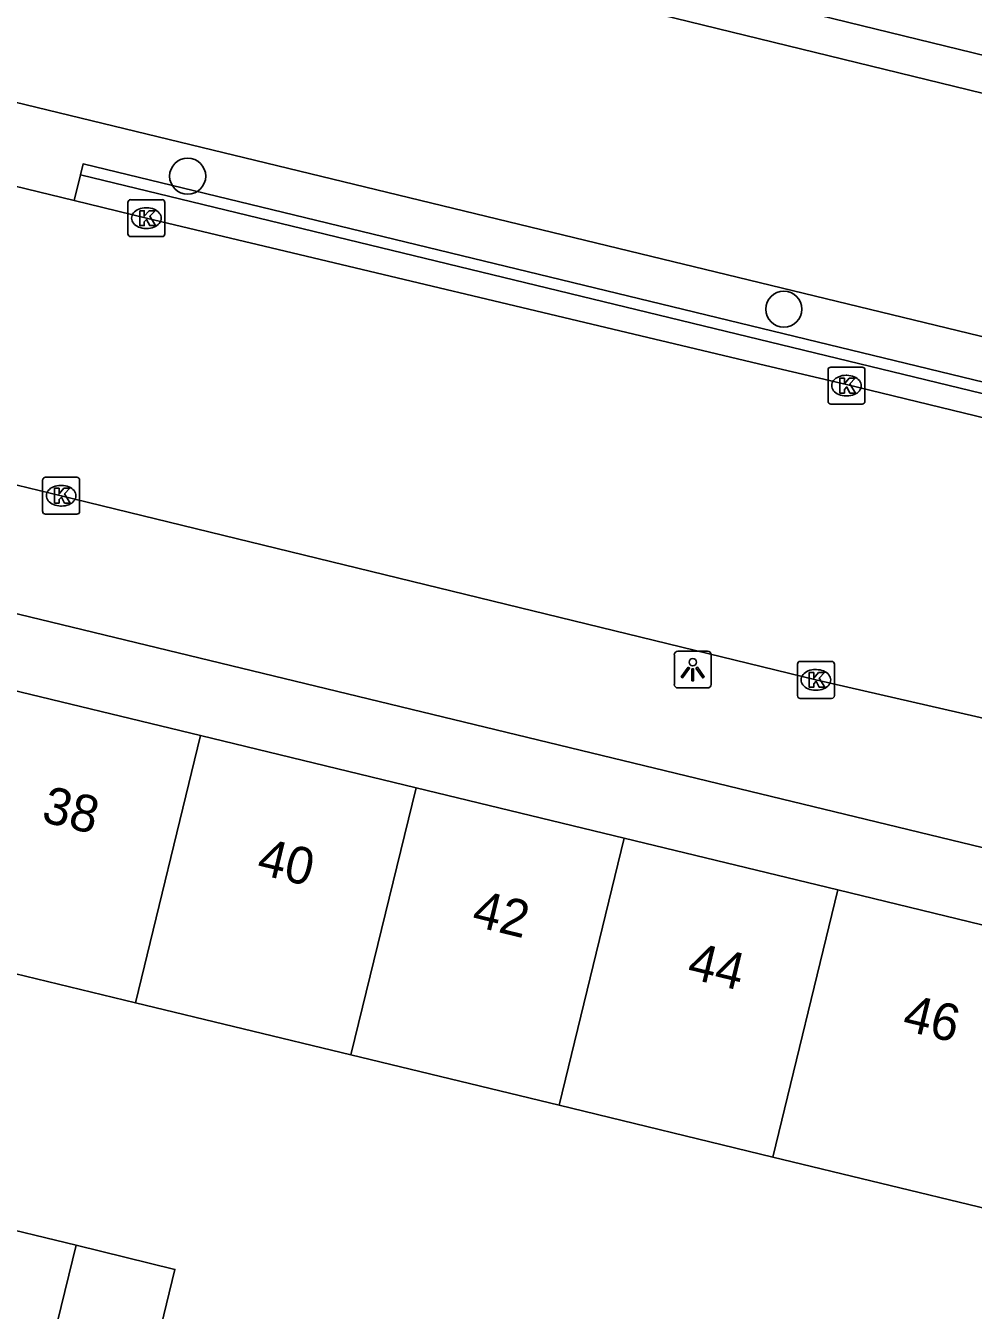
# Model space of a CAD drawing. Extents: x 162812 to 163818, y 381639 to 382470.
# Drawn here: x 163350.81 to 163376.49, y 382263.66 to 382298.47 of the extents above; entities that cross this region are included whole.
import ezdxf

# ---------------------------------------------------------------- set-up
doc = ezdxf.new("R2010")
doc.units = 0
for name, color, linetype in [('IMGEO_Boom', 7, 'Continuous'), ('IMGEO_Groenvoorziening', 7, 'Continuous'), ('IMGEO_Haag', 7, 'Continuous'), ('IMGEO_Kolk', 7, 'Continuous'), ('IMGEO_Lichtpunt', 7, 'Continuous'), ('IMGEO_Muur', 7, 'Continuous'), ('IMGEO_Pand', 7, 'Continuous'), ('IMGEO_Pand_nummerreeks', 7, 'Continuous'), ('IMGEO_Rijbaan_lokaal_gesloten', 7, 'Continuous'), ('IMGEO_Voetpad_open', 7, 'Continuous'), ('IMGEO_Waterloop', 7, 'Continuous')]:
    doc.layers.add(name, color=color, linetype=linetype)

msp = doc.modelspace()

# ---------------------------------------------------------------- linework, layer by layer
at = {"layer": 'IMGEO_Boom'}
for centre in [(163355.197, 382294.391), (163371.351, 382290.786)]:
    msp.add_circle(centre, 0.489, dxfattribs=at)
at = {"layer": 'IMGEO_Groenvoorziening'}
for points in [[(163321.09, 382310.224), (163499.763, 382266.618), (163515.133, 382262.867)], [(163454.527, 382271.183), (163319.582, 382303.902)], [(163388.463, 382285.657), (163388.534, 382285.949), (163352.363, 382294.719), (163352.293, 382294.427)]]:
    msp.add_lwpolyline(points, dxfattribs=at)
at = {"layer": 'IMGEO_Haag'}
for points in [[(163352.293, 382294.427), (163352.124, 382293.728)], [(163352.293, 382294.427), (163388.463, 382285.657)]]:
    msp.add_lwpolyline(points, dxfattribs=at)
at = {"layer": 'IMGEO_Kolk'}
for p, q in [((163353.652, 382293.752), (163354.504, 382293.752)), ((163353.577, 382292.826), (163353.577, 382293.678)), ((163354.065, 382293.532), (163354.09, 382293.532)), ((163354.578, 382293.678), (163354.578, 382292.826)), ((163354.504, 382292.752), (163353.652, 382292.752)), ((163354.088, 382292.972), (163354.063, 382292.972)), ((163372.624, 382289.213), (163373.476, 382289.213)), ((163372.549, 382288.287), (163372.549, 382289.139)), ((163373.037, 382288.993), (163373.062, 382288.993)), ((163373.55, 382289.139), (163373.55, 382288.287)), ((163373.476, 382288.213), (163372.624, 382288.213)), ((163373.06, 382288.433), (163373.035, 382288.433)), ((163351.268, 382285.305), (163351.268, 382286.157)), ((163351.343, 382286.231), (163352.195, 382286.231)), ((163352.269, 382286.157), (163352.269, 382285.305)), ((163351.756, 382286.011), (163351.781, 382286.011)), ((163351.779, 382285.451), (163351.754, 382285.451)), ((163352.195, 382285.231), (163351.343, 382285.231)), ((163371.72, 382280.314), (163371.72, 382281.166)), ((163371.795, 382281.24), (163372.647, 382281.24)), ((163372.721, 382281.166), (163372.721, 382280.314)), ((163372.208, 382281.02), (163372.233, 382281.02)), ((163372.231, 382280.46), (163372.206, 382280.46)), ((163372.647, 382280.24), (163371.795, 382280.24))]:
    msp.add_line(p, q, dxfattribs=at)
for points in [[(163353.652, 382293.752), (163354.504, 382293.752)], [(163353.577, 382292.826), (163353.577, 382293.678)], [(163353.898, 382293.452), (163354.021, 382293.452), (163354.021, 382293.301), (163354.151, 382293.452), (163354.315, 382293.452), (163354.169, 382293.301), (163354.322, 382293.052), (163354.17, 382293.052), (163354.085, 382293.216), (163354.021, 382293.149), (163354.021, 382293.052), (163353.898, 382293.052), (163353.898, 382293.452)], [(163354.578, 382293.678), (163354.578, 382292.826)], [(163354.504, 382292.752), (163353.652, 382292.752)], [(163372.624, 382289.213), (163373.476, 382289.213)], [(163372.549, 382288.287), (163372.549, 382289.139)], [(163372.87, 382288.913), (163372.993, 382288.913), (163372.993, 382288.762), (163373.123, 382288.913), (163373.287, 382288.913), (163373.141, 382288.762), (163373.294, 382288.513), (163373.142, 382288.513), (163373.057, 382288.677), (163372.993, 382288.61), (163372.993, 382288.513), (163372.87, 382288.513), (163372.87, 382288.913)], [(163373.55, 382289.139), (163373.55, 382288.287)], [(163373.476, 382288.213), (163372.624, 382288.213)], [(163351.268, 382285.305), (163351.268, 382286.157)], [(163351.343, 382286.231), (163352.195, 382286.231)], [(163352.269, 382286.157), (163352.269, 382285.305)], [(163351.589, 382285.931), (163351.712, 382285.931), (163351.712, 382285.78), (163351.842, 382285.931), (163352.006, 382285.931), (163351.86, 382285.78), (163352.013, 382285.531), (163351.861, 382285.531), (163351.776, 382285.695), (163351.712, 382285.628), (163351.712, 382285.531), (163351.589, 382285.531), (163351.589, 382285.931)], [(163352.195, 382285.231), (163351.343, 382285.231)], [(163371.72, 382280.314), (163371.72, 382281.166)], [(163371.795, 382281.24), (163372.647, 382281.24)], [(163372.721, 382281.166), (163372.721, 382280.314)], [(163372.041, 382280.94), (163372.164, 382280.94), (163372.164, 382280.789), (163372.294, 382280.94), (163372.458, 382280.94), (163372.312, 382280.789), (163372.465, 382280.54), (163372.313, 382280.54), (163372.228, 382280.704), (163372.164, 382280.637), (163372.164, 382280.54), (163372.041, 382280.54), (163372.041, 382280.94)], [(163372.647, 382280.24), (163371.795, 382280.24)]]:
    msp.add_lwpolyline(points, dxfattribs=at)
for centre, start, end in [((163353.654, 382293.676), 91.552, 178.448), ((163353.654, 382293.676), 91.552, 178.448), ((163354.502, 382293.676), 1.552, 88.448), ((163354.502, 382293.676), 1.552, 88.448), ((163353.654, 382292.828), 181.552, 268.448), ((163353.654, 382292.828), 181.552, 268.448), ((163354.502, 382292.828), 271.552, 358.448), ((163354.502, 382292.828), 271.552, 358.448), ((163372.626, 382289.137), 91.552, 178.448), ((163372.626, 382289.137), 91.552, 178.448), ((163373.474, 382289.137), 1.552, 88.448), ((163373.474, 382289.137), 1.552, 88.448), ((163372.626, 382288.289), 181.552, 268.448), ((163372.626, 382288.289), 181.552, 268.448), ((163373.474, 382288.289), 271.552, 358.448), ((163373.474, 382288.289), 271.552, 358.448), ((163351.345, 382286.155), 91.552, 178.448), ((163351.345, 382286.155), 91.552, 178.448), ((163352.193, 382286.155), 1.552, 88.448), ((163352.193, 382286.155), 1.552, 88.448), ((163351.345, 382285.307), 181.552, 268.448), ((163351.345, 382285.307), 181.552, 268.448), ((163352.193, 382285.307), 271.552, 358.448), ((163352.193, 382285.307), 271.552, 358.448), ((163371.797, 382281.164), 91.552, 178.448), ((163371.797, 382281.164), 91.552, 178.448), ((163372.645, 382281.164), 1.552, 88.448), ((163372.645, 382281.164), 1.552, 88.448), ((163371.797, 382280.316), 181.552, 268.448), ((163371.797, 382280.316), 181.552, 268.448), ((163372.645, 382280.316), 271.552, 358.448), ((163372.645, 382280.316), 271.552, 358.448)]:
    msp.add_arc(centre, 0.0765, start, end, dxfattribs=at)
for centre, major_axis, ratio, start_param, end_param in [((163354.064, 382293.252), (-0.387, 0.002), 0.722429, 4.712389, 7.853982), ((163354.089, 382293.252), (-0.39, 0.002), 0.717154, 1.570796, 4.712389), ((163373.036, 382288.713), (-0.387, 0.002), 0.722429, 4.712389, 7.853982), ((163373.061, 382288.713), (-0.39, 0.002), 0.717154, 1.570796, 4.712389), ((163351.755, 382285.731), (-0.387, 0.002), 0.722429, 4.712389, 7.853982), ((163351.78, 382285.731), (-0.39, 0.002), 0.717154, 1.570796, 4.712389), ((163372.207, 382280.74), (-0.387, 0.002), 0.722429, 4.712389, 7.853982), ((163372.232, 382280.74), (-0.39, 0.002), 0.717154, 1.570796, 4.712389)]:
    msp.add_ellipse(centre, major_axis=major_axis, ratio=ratio, start_param=start_param, end_param=end_param, dxfattribs=at)
at = {"layer": 'IMGEO_Lichtpunt'}
for p, q in [((163369.287, 382281.517), (163368.479, 382281.517)), ((163369.287, 382281.517), (163368.479, 382281.517)), ((163368.385, 382281.422), (163368.385, 382280.615)), ((163368.385, 382281.422), (163368.385, 382280.615)), ((163369.381, 382280.615), (163369.381, 382281.422)), ((163369.381, 382280.615), (163369.381, 382281.422)), ((163368.479, 382280.521), (163369.287, 382280.521)), ((163368.479, 382280.521), (163369.287, 382280.521))]:
    msp.add_line(p, q, dxfattribs=at)
for points in [[(163368.759, 382281.086), (163368.798, 382281.058), (163368.61, 382280.796), (163368.572, 382280.823), (163368.759, 382281.086)], [(163368.861, 382281.038), (163368.908, 382281.038), (163368.908, 382280.716), (163368.861, 382280.716), (163368.861, 382281.038)], [(163368.971, 382281.058), (163369.009, 382281.085), (163369.196, 382280.823), (163369.157, 382280.795), (163368.971, 382281.058)]]:
    msp.add_lwpolyline(points, dxfattribs=at)
msp.add_circle((163368.884, 382281.22), 0.0994, dxfattribs=at)
for centre, start, end in [((163368.479, 382281.422), 90, 180), ((163368.479, 382281.422), 90, 180), ((163369.287, 382281.422), 0, 90), ((163369.287, 382281.422), 0, 90), ((163368.479, 382280.615), 180, 270), ((163368.479, 382280.615), 180, 270), ((163369.287, 382280.615), 270, 0), ((163369.287, 382280.615), 270, 360)]:
    msp.add_arc(centre, 0.0946, start, end, dxfattribs=at)
at = {"layer": 'IMGEO_Muur'}
msp.add_lwpolyline([(163319.582, 382303.902), (163454.527, 382271.183)], dxfattribs=at)
at = {"layer": 'IMGEO_Pand'}
for points in [[(163355.549, 382279.231), (163349.857, 382280.609)], [(163353.786, 382271.992), (163355.549, 382279.231)], [(163361.386, 382277.817), (163355.549, 382279.231)], [(163361.386, 382277.817), (163359.623, 382270.578)], [(163367.026, 382276.452), (163361.386, 382277.817)], [(163367.026, 382276.452), (163365.264, 382269.212)], [(163372.818, 382275.049), (163367.026, 382276.452)], [(163371.056, 382267.81), (163372.818, 382275.049)], [(163378.653, 382273.636), (163372.818, 382275.049)], [(163353.786, 382271.992), (163348.115, 382273.365)], [(163359.623, 382270.578), (163353.786, 382271.992)], [(163365.264, 382269.212), (163359.623, 382270.578)], [(163371.056, 382267.81), (163365.264, 382269.212)], [(163376.89, 382266.397), (163371.056, 382267.81)], [(163348.719, 382262.318), (163349.625, 382266.04), (163352.175, 382265.419)], [(163351.268, 382261.697), (163352.175, 382265.419)], [(163352.175, 382265.419), (163354.853, 382264.767), (163353.947, 382261.045)]]:
    msp.add_lwpolyline(points, dxfattribs=at)
at = {"layer": 'IMGEO_Rijbaan_lokaal_gesloten'}
for points in [[(163352.124, 382293.728), (163345.905, 382295.242)], [(163388.331, 382285.029), (163373.046, 382288.743), (163370.856, 382289.256), (163354.078, 382293.252), (163352.124, 382293.728)], [(163390.314, 382276.403), (163384.375, 382277.84), (163378.286, 382279.347), (163372.221, 382280.741), (163351.77, 382285.731), (163346.697, 382286.96)]]:
    msp.add_lwpolyline(points, dxfattribs=at)
at = {"layer": 'IMGEO_Voetpad_open'}
msp.add_lwpolyline([(163350.348, 382282.582), (163385.343, 382274.108)], dxfattribs=at)
at = {"layer": 'IMGEO_Waterloop'}
msp.add_lwpolyline([(163515.373, 382263.837), (163500, 382267.589), (163321.322, 382311.196)], dxfattribs=at)

# ---------------------------------------------------------------- texts
at = {"layer": 'IMGEO_Pand_nummerreeks'}
for s, p in [('38', (163351.201, 382276.908)), ('40', (163357.033, 382275.496)), ('42', (163362.86, 382274.086)), ('44', (163368.695, 382272.672)), ('46', (163374.528, 382271.26))]:
    msp.add_text(s, height=1, rotation=346.3879, dxfattribs=at).set_placement(p)

doc.saveas('drawing.dxf')
